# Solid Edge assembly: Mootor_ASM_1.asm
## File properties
Author: KULL
Template: Iso Metric Assembly.asm
Last saved by: KULL
Revision: 42
Application: Solid Edge
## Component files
Kepsude laager.par
Keps.par
Keps2.par
Kolb1.par
hiplokk 2.par
ntv6ll.par
Plokikaas_2 thin wall_topcut.par
ljalaske viisk.par
livann1.par
livanni_polt_1.par
ikkega.par
lli muhvid.par
Crancshaft bearing.asm
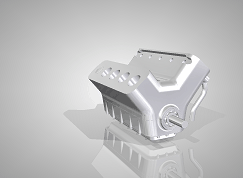
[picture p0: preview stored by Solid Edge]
